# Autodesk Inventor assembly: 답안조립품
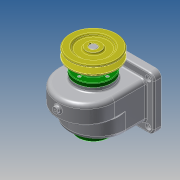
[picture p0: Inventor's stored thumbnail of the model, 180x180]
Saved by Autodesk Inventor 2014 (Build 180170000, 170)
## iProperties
Created: 2017-11
Part Number: 답안조립품
Document SubType Name: Assembly
Designer: kb543-05
Author: kb543-05
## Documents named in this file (14)
- C:\Users\kb543-05\Desktop\471107V1001\답안조립품.iam
- C:\Users\kb543-05\Desktop\471107V1001\본체.ipt
- C:\Users\kb543-05\Desktop\471107V1001\축.ipt
- C:\Users\kb543-05\Desktop\471107V1001\스퍼기어.ipt
- C:\Users\kb543-05\Desktop\471107V1001\베어링 6002.ipt
- C:\Users\kb543-05\Desktop\471107V1001\뒤커버.ipt
- C:\Users\kb543-05\Desktop\471107V1001\볼트 M3 x 8.ipt
- C:\Users\kb543-05\Desktop\471107V1001\키 - 6 x 6 x 22.ipt
- C:\Users\kb543-05\Desktop\471107V1001\앞커버.ipt
- C:\Users\kb543-05\Desktop\471107V1001\키 - 5 x 5 x 18.ipt
- C:\Users\kb543-05\Desktop\471107V1001\오일 실 15 30 7.ipt
- C:\Users\kb543-05\Desktop\471107V1001\V-벨트풀리.ipt
- C:\Users\kb543-05\Desktop\471107V1001\멈춤나사 - M4 x 10.ipt
- 멈춤나사 - M4 x 10.ipt
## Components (1 placed, 1 different names)
1. V-벨트풀리:1
